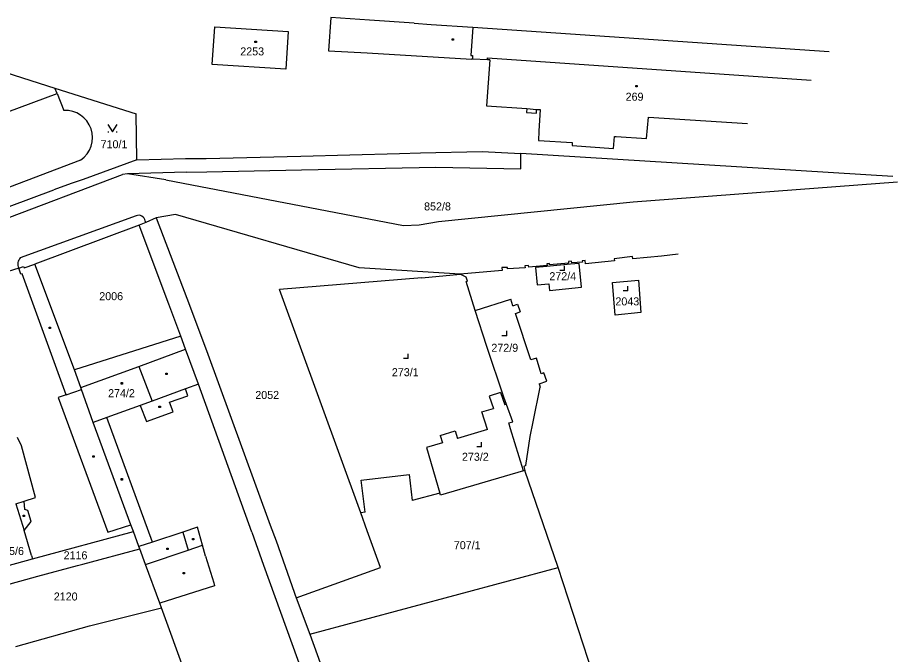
# Model space of a CAD drawing. Extents: x -711879 to -711361, y -1048782 to -1048177.
# Drawn here: x -711557.6 to -711370.9, y -1048599.8 to -1048464.6 of the extents above; entities that cross this region are included whole.
import ezdxf

# ---------------------------------------------------------------- set-up
doc = ezdxf.new("R2010")
doc.units = 0
for name, color, linetype in [('Vrstva 1', 7, 'Continuous'), ('Vrstva 14', 7, 'Continuous'), ('Vrstva 15', 7, 'Continuous'), ('Vrstva 2', 7, 'Continuous'), ('Vrstva 23', 7, 'Continuous'), ('Vrstva 25', 7, 'Continuous'), ('Vrstva 46', 7, 'Continuous')]:
    doc.layers.add(name, color=color, linetype=linetype)

msp = doc.modelspace()

# ---------------------------------------------------------------- linework, layer by layer
at = {"layer": 'Vrstva 1'}
for p, q in [((-711473.47, -1048465.82), (-711482.93, -1048465.18)), ((-711473.47, -1048465.82), (-711469.86, -1048466.07)), ((-711469.86, -1048466.07), (-711460.98, -1048466.67)), ((-711460.98, -1048466.67), (-711385.33, -1048471.82)), ((-711575.44, -1048471.4), (-711549.72, -1048479.57)), ((-711483.41, -1048472.14), (-711461.31, -1048473.42)), ((-711461.08, -1048473.43), (-711461.31, -1048473.42)), ((-711457.91, -1048473.59), (-711461.08, -1048473.43)), ((-711457.37, -1048473.6), (-711458.13, -1048483.34)), ((-711457.37, -1048473.6), (-711457.91, -1048473.59)), ((-711549.25, -1048480.75), (-711549.72, -1048479.57)), ((-711549.72, -1048479.57), (-711532.44, -1048485.06)), ((-711549.25, -1048480.75), (-711547.81, -1048484.31)), ((-711458.13, -1048483.34), (-711449.56, -1048483.95)), ((-711447.47, -1048484.1), (-711446.7, -1048484.15)), ((-711532.35, -1048494.8), (-711532.44, -1048485.06)), ((-711446.7, -1048484.15), (-711446.97, -1048488.76)), ((-711424.12, -1048490.31), (-711423.75, -1048485.73)), ((-711423.75, -1048485.73), (-711402.67, -1048487.12)), ((-711430.94, -1048489.85), (-711430.57, -1048489.87)), ((-711430.57, -1048489.87), (-711424.12, -1048490.31)), ((-711476.59, -1048493.47), (-711472.1, -1048493.36)), ((-711472.1, -1048493.36), (-711459, -1048493.05)), ((-711459, -1048493.05), (-711450.84, -1048493.44)), ((-711371.84, -1048498.35), (-711450.84, -1048493.44)), ((-711544.25, -1048494.85), (-711560.87, -1048501.16)), ((-711532.35, -1048494.8), (-711543.69, -1048498.96)), ((-711532.35, -1048494.8), (-711522.01, -1048494.53)), ((-711522.01, -1048494.53), (-711517.63, -1048494.53)), ((-711517.63, -1048494.53), (-711497.52, -1048494.02)), ((-711497.52, -1048494.02), (-711487.1, -1048493.75)), ((-711487.1, -1048493.75), (-711476.59, -1048493.47)), ((-711543.69, -1048498.96), (-711546.24, -1048499.86)), ((-711546.24, -1048499.86), (-711549.96, -1048501.2)), ((-711559.44, -1048504.71), (-711549.96, -1048501.2)), ((-711524.13, -1048506.41), (-711528.19, -1048507.13)), ((-711485.15, -1048517.73), (-711524.13, -1048506.41)), ((-711530.44, -1048508.12), (-711531.84, -1048508.65)), ((-711528.19, -1048507.13), (-711530.44, -1048508.12)), ((-711528.19, -1048507.13), (-711521.72, -1048524.2)), ((-711531.84, -1048508.65), (-711553.95, -1048516.92)), ((-711525.53, -1048525.42), (-711531.84, -1048508.65)), ((-711427.11, -1048515.34), (-711430.99, -1048515.8)), ((-711430.99, -1048515.8), (-711430.95, -1048516.28)), ((-711427.05, -1048515.84), (-711427.11, -1048515.34)), ((-711420.96, -1048515.29), (-711427.05, -1048515.84)), ((-711417.45, -1048514.81), (-711420.96, -1048515.29)), ((-711557.41, -1048517.79), (-711556.37, -1048517.43)), ((-711556.37, -1048517.43), (-711556.22, -1048517.76)), ((-711556.22, -1048517.76), (-711553.95, -1048516.92)), ((-711545.57, -1048539.39), (-711553.95, -1048516.92)), ((-711463.67, -1048519.09), (-711485.15, -1048517.73)), ((-711453.68, -1048517.63), (-711454.83, -1048517.69)), ((-711454.83, -1048517.69), (-711454.78, -1048518.29)), ((-711453.64, -1048517.98), (-711453.68, -1048517.63)), ((-711449.16, -1048517.22), (-711449.96, -1048517.32)), ((-711449.96, -1048517.32), (-711449.91, -1048517.74)), ((-711449.11, -1048517.59), (-711449.16, -1048517.22)), ((-711445.26, -1048517.25), (-711449.11, -1048517.59)), ((-711445.3, -1048517.43), (-711447.73, -1048517.67)), ((-711447.73, -1048517.67), (-711447.34, -1048521.37)), ((-711440.3, -1048516.97), (-711445.3, -1048517.43)), ((-711444.74, -1048516.84), (-711445.28, -1048516.89)), ((-711445.28, -1048516.89), (-711445.26, -1048517.25)), ((-711444.71, -1048517.11), (-711444.74, -1048516.84)), ((-711440.71, -1048516.72), (-711444.71, -1048517.11)), ((-711440.05, -1048516.33), (-711440.73, -1048516.39)), ((-711440.73, -1048516.39), (-711440.71, -1048516.72)), ((-711438.44, -1048516.83), (-711440.3, -1048516.97)), ((-711440.01, -1048516.66), (-711440.05, -1048516.33)), ((-711437.75, -1048516.54), (-711440.01, -1048516.66)), ((-711437.92, -1048521.86), (-711438.44, -1048516.83)), ((-711437.13, -1048516.17), (-711437.77, -1048516.22)), ((-711437.77, -1048516.22), (-711437.75, -1048516.54)), ((-711437.08, -1048516.85), (-711437.13, -1048516.17)), ((-711430.95, -1048516.28), (-711437.08, -1048516.85)), ((-711557.41, -1048517.79), (-711560.97, -1048518.96)), ((-711471.8, -1048519.84), (-711463.67, -1048519.09)), ((-711454.78, -1048518.29), (-711463.67, -1048519.09)), ((-711462.39, -1048519.72), (-711463.67, -1048519.09)), ((-711449.91, -1048517.74), (-711453.64, -1048517.98)), ((-711471.8, -1048519.84), (-711502.02, -1048522.33)), ((-711462.42, -1048520.66), (-711462.13, -1048520.55)), ((-711460.54, -1048526.78), (-711462.42, -1048520.66)), ((-711462.13, -1048520.55), (-711462.39, -1048519.72)), ((-711447.34, -1048521.37), (-711444.88, -1048521.15)), ((-711444.88, -1048521.15), (-711444.75, -1048522.51)), ((-711431.35, -1048520.88), (-711425.82, -1048520.37)), ((-711430.8, -1048527.75), (-711431.35, -1048520.88)), ((-711425.82, -1048520.37), (-711425.32, -1048527.24)), ((-711484.79, -1048569.75), (-711502.02, -1048522.33)), ((-711444.75, -1048522.51), (-711437.92, -1048521.86)), ((-711521.72, -1048524.2), (-711517.53, -1048535.25)), ((-711460.54, -1048526.78), (-711452.95, -1048524.36)), ((-711452.48, -1048525.77), (-711452.95, -1048524.36)), ((-711523.01, -1048532.21), (-711525.53, -1048525.42)), ((-711458.05, -1048534.42), (-711460.54, -1048526.78)), ((-711452.48, -1048525.77), (-711451.53, -1048525.45)), ((-711451.53, -1048525.45), (-711450.95, -1048527.1)), ((-711451.93, -1048527.44), (-711450.95, -1048527.1)), ((-711448.68, -1048537.29), (-711451.93, -1048527.44)), ((-711425.32, -1048527.24), (-711430.8, -1048527.75)), ((-711523.01, -1048532.21), (-711545.57, -1048539.39)), ((-711521.97, -1048535.01), (-711523.01, -1048532.21)), ((-711454.4, -1048545.16), (-711458.05, -1048534.42)), ((-711519.23, -1048542.39), (-711521.97, -1048535.01)), ((-711517.53, -1048535.25), (-711509.85, -1048556.43)), ((-711447.52, -1048536.9), (-711448.68, -1048537.29)), ((-711446.49, -1048540.23), (-711447.52, -1048536.9)), ((-711544.23, -1048543.15), (-711545.57, -1048539.39)), ((-711445.91, -1048540), (-711446.49, -1048540.23)), ((-711445.29, -1048541.76), (-711445.91, -1048540)), ((-711446.94, -1048542.35), (-711445.29, -1048541.76)), ((-711544.1, -1048543.52), (-711544.23, -1048543.15)), ((-711541.58, -1048550.58), (-711544.1, -1048543.52)), ((-711519.23, -1048542.39), (-711522.03, -1048543.41)), ((-711521.5, -1048544.88), (-711522.03, -1048543.41)), ((-711507.9, -1048573.82), (-711519.23, -1048542.39)), ((-711448.2, -1048550.39), (-711446.71, -1048543.05)), ((-711446.94, -1048542.35), (-711446.87, -1048542.57)), ((-711446.87, -1048542.57), (-711446.71, -1048543.05)), ((-711525.38, -1048546.26), (-711521.5, -1048544.88)), ((-711455.14, -1048544.19), (-711457.51, -1048544.97)), ((-711457.51, -1048544.97), (-711456.65, -1048547.57)), ((-711455.14, -1048544.19), (-711454.21, -1048546.83)), ((-711453.87, -1048546.71), (-711454.4, -1048545.16)), ((-711531.59, -1048546.92), (-711538.69, -1048549.52)), ((-711531.59, -1048546.92), (-711530.27, -1048550.33)), ((-711524.62, -1048548.3), (-711525.38, -1048546.26)), ((-711459.12, -1048548.31), (-711456.65, -1048547.57)), ((-711453.87, -1048546.71), (-711454.21, -1048546.83)), ((-711452.49, -1048550.39), (-711453.87, -1048546.71)), ((-711530.27, -1048550.33), (-711524.62, -1048548.3)), ((-711457.86, -1048552.01), (-711459.12, -1048548.31)), ((-711533.58, -1048572.27), (-711541.58, -1048550.58)), ((-711529.01, -1048575.92), (-711538.69, -1048549.52)), ((-711453.39, -1048550.65), (-711452.49, -1048550.39)), ((-711453, -1048551.92), (-711453.39, -1048550.65)), ((-711448.82, -1048553.5), (-711448.2, -1048550.39)), ((-711467.92, -1048553.33), (-711464.78, -1048552.31)), ((-711464.78, -1048552.31), (-711464.24, -1048553.92)), ((-711457.86, -1048552.01), (-711464.24, -1048553.92)), ((-711450.27, -1048560.84), (-711453, -1048551.92)), ((-711556.81, -1048555.48), (-711557.67, -1048553.71)), ((-711467.43, -1048554.88), (-711470.82, -1048555.89)), ((-711467.92, -1048553.33), (-711467.43, -1048554.88)), ((-711449.72, -1048559.71), (-711448.82, -1048553.5)), ((-711553.85, -1048566.46), (-711556.81, -1048555.48)), ((-711509.85, -1048556.43), (-711504.02, -1048572.33)), ((-711470.82, -1048555.89), (-711468.01, -1048565.56)), ((-711449.72, -1048559.71), (-711450.2, -1048559.86)), ((-711450.2, -1048559.86), (-711449.94, -1048560.74)), ((-711484.7, -1048562.79), (-711474.54, -1048561.6)), ((-711474.54, -1048561.6), (-711473.86, -1048567.13)), ((-711450.27, -1048560.84), (-711467.89, -1048565.98)), ((-711449.94, -1048560.74), (-711450.27, -1048560.84)), ((-711442.86, -1048581.35), (-711449.94, -1048560.74)), ((-711483.89, -1048569.55), (-711484.7, -1048562.79)), ((-711468.01, -1048565.56), (-711473.86, -1048567.13)), ((-711467.89, -1048565.98), (-711468.01, -1048565.56)), ((-711558, -1048567.81), (-711556.26, -1048567.22)), ((-711556.26, -1048567.22), (-711553.85, -1048566.46)), ((-711483.89, -1048569.55), (-711484.79, -1048569.75)), ((-711483.41, -1048573.55), (-711484.79, -1048569.75)), ((-711554.45, -1048579.51), (-711533.06, -1048573.69)), ((-711533.06, -1048573.69), (-711533.58, -1048572.27)), ((-711531.88, -1048576.89), (-711533.06, -1048573.69)), ((-711519.46, -1048572.8), (-711522.53, -1048573.8)), ((-711518.39, -1048576.61), (-711519.46, -1048572.8)), ((-711504.02, -1048572.33), (-711502.76, -1048575.7)), ((-711480.59, -1048581.32), (-711483.41, -1048573.55)), ((-711522.53, -1048573.8), (-711529.01, -1048575.92)), ((-711507.9, -1048573.82), (-711505.42, -1048580.81)), ((-711543.79, -1048580.61), (-711531.71, -1048577.35)), ((-711531.71, -1048577.35), (-711531.88, -1048576.89)), ((-711530.48, -1048580.69), (-711531.71, -1048577.35)), ((-711517.73, -1048578.95), (-711518.39, -1048576.61)), ((-711502.76, -1048575.7), (-711498.95, -1048586.55)), ((-711517.73, -1048578.95), (-711516.01, -1048584.55)), ((-711562.83, -1048581.76), (-711554.45, -1048579.51)), ((-711553.36, -1048583.2), (-711544.91, -1048580.91)), ((-711544.91, -1048580.91), (-711543.79, -1048580.61)), ((-711527.46, -1048588.87), (-711530.48, -1048580.69)), ((-711505.42, -1048580.81), (-711488.95, -1048626.45)), ((-711498.5, -1048587.73), (-711482.4, -1048581.96)), ((-711495.62, -1048595.46), (-711442.86, -1048581.35)), ((-711482.4, -1048581.96), (-711480.59, -1048581.32)), ((-711434.36, -1048607.51), (-711442.86, -1048581.35)), ((-711561.81, -1048585.49), (-711553.36, -1048583.2)), ((-711516.01, -1048584.55), (-711515.82, -1048585.22)), ((-711515.82, -1048585.22), (-711527.46, -1048588.87)), ((-711498.95, -1048586.55), (-711498.79, -1048586.96)), ((-711498.79, -1048586.96), (-711498.5, -1048587.73)), ((-711498.5, -1048587.73), (-711495.62, -1048595.46)), ((-711542.36, -1048593.72), (-711527.11, -1048589.92)), ((-711527.11, -1048589.92), (-711527.46, -1048588.87)), ((-711520.21, -1048608.66), (-711527.11, -1048589.92)), ((-711557.98, -1048598.11), (-711542.36, -1048593.72)), ((-711495.62, -1048595.46), (-711482.57, -1048631.65))]:
    msp.add_line(p, q, dxfattribs=at)
for points in [[(-711482.93, -1048465.18), (-711491.12, -1048464.63), (-711491.67, -1048471.66), (-711483.41, -1048472.14)], [(-711515.8, -1048466.56), (-711500.18, -1048467.58), (-711500.7, -1048475.56), (-711516.32, -1048474.55), (-711515.8, -1048466.56)], [(-711449.56, -1048483.95), (-711449.61, -1048484.76), (-711447.52, -1048484.9), (-711447.47, -1048484.1)], [(-711446.97, -1048488.76), (-711447.1, -1048490.68), (-711439.89, -1048491.17), (-711439.93, -1048491.77), (-711431.11, -1048492.38), (-711430.94, -1048489.85)]]:
    msp.add_lwpolyline(points, dxfattribs=at)
msp.add_arc((-711547.524, -1048490.085), 5.782, 304.49178, 92.83413, dxfattribs=at)
at = {"layer": 'Vrstva 2'}
for p, q in [((-711460.98, -1048466.67), (-711461.45, -1048472.65)), ((-711461.45, -1048472.65), (-711461.04, -1048472.65)), ((-711461.04, -1048472.65), (-711461.08, -1048473.43)), ((-711457.91, -1048473.59), (-711457.89, -1048473.19)), ((-711457.89, -1048473.19), (-711389.22, -1048477.89)), ((-711559.72, -1048484.64), (-711549.25, -1048480.75)), ((-711449.56, -1048483.95), (-711447.47, -1048484.1)), ((-711450.78, -1048496.73), (-711450.84, -1048493.44)), ((-711517.49, -1048497.39), (-711497.39, -1048496.93)), ((-711497.39, -1048496.93), (-711468.85, -1048496.38)), ((-711468.85, -1048496.38), (-711450.78, -1048496.73)), ((-711562.32, -1048508.09), (-711535.4, -1048497.92)), ((-711534.31, -1048497.75), (-711535.4, -1048497.92)), ((-711521.87, -1048497.44), (-711534.31, -1048497.75)), ((-711526.19, -1048499.09), (-711534.31, -1048497.75)), ((-711521.87, -1048497.44), (-711517.49, -1048497.39)), ((-711526.19, -1048499.09), (-711475.74, -1048508.78)), ((-711426.99, -1048503.71), (-711370.88, -1048499.49)), ((-711468.31, -1048507.91), (-711426.99, -1048503.71)), ((-711532.48, -1048506.69), (-711557.07, -1048515.58)), ((-711530.44, -1048508.12), (-711530.54, -1048507.78)), ((-711472.38, -1048508.62), (-711468.31, -1048507.91)), ((-711475.74, -1048508.78), (-711472.38, -1048508.62)), ((-711556.96, -1048519.09), (-711557.41, -1048517.79)), ((-711556.7, -1048518.99), (-711556.96, -1048519.09)), ((-711547.3, -1048544.68), (-711556.7, -1048518.99)), ((-711531.9, -1048538.64), (-711521.97, -1048535.01)), ((-711544.23, -1048543.15), (-711531.9, -1048538.64)), ((-711531.9, -1048538.64), (-711529.08, -1048546)), ((-711547.3, -1048544.68), (-711544.1, -1048543.52)), ((-711522.03, -1048543.41), (-711529.08, -1048546)), ((-711547.3, -1048544.68), (-711549.03, -1048545.28)), ((-711549.03, -1048545.28), (-711538.47, -1048573.84)), ((-711529.08, -1048546), (-711531.59, -1048546.92)), ((-711538.69, -1048549.52), (-711541.58, -1048550.58)), ((-711558, -1048567.81), (-711556.25, -1048573.47)), ((-711556.08, -1048568.99), (-711556.26, -1048567.22)), ((-711555.5, -1048569.22), (-711556.08, -1048568.99)), ((-711554.78, -1048571.56), (-711555.5, -1048569.22)), ((-711556.25, -1048573.47), (-711554.78, -1048571.56)), ((-711554.67, -1048578.78), (-711556.25, -1048573.47)), ((-711538.47, -1048573.84), (-711533.58, -1048572.27)), ((-711522.53, -1048573.8), (-711521.43, -1048577.64)), ((-711529.01, -1048575.92), (-711531.88, -1048576.89)), ((-711521.43, -1048577.64), (-711518.39, -1048576.61)), ((-711554.67, -1048578.78), (-711554.45, -1048579.51)), ((-711530.48, -1048580.69), (-711521.43, -1048577.64))]:
    msp.add_line(p, q, dxfattribs=at)
for centre, radius, start, end in [((-711531.944, -1048508.007), 1.422, 9.20144, 112.13915), ((-711555.629, -1048516.933), 1.977, 136.81148, 205.69619)]:
    msp.add_arc(centre, radius, start, end, dxfattribs=at)
at = {"layer": 'Vrstva 23'}
for p, q in [((-711538.48, -1048487.35), (-711537.48, -1048488.85)), ((-711537.48, -1048488.85), (-711536.48, -1048487.35)), ((-711538.48, -1048488.85), (-711538.28, -1048488.85)), ((-711536.68, -1048488.85), (-711536.48, -1048488.85)), ((-711441.52, -1048518.33), (-711441.52, -1048517.33)), ((-711441.52, -1048518.33), (-711442.52, -1048518.33)), ((-711428.07, -1048522.64), (-711429.07, -1048522.64)), ((-711428.07, -1048522.64), (-711428.07, -1048521.64)), ((-711453.82, -1048532.13), (-711454.82, -1048532.13)), ((-711453.82, -1048532.13), (-711453.82, -1048531.13)), ((-711474.72, -1048536.99), (-711474.72, -1048535.99)), ((-711474.72, -1048536.99), (-711475.72, -1048536.99)), ((-711459.15, -1048555.75), (-711459.15, -1048554.75)), ((-711459.15, -1048555.75), (-711460.15, -1048555.75))]:
    msp.add_line(p, q, dxfattribs=at)
at = {"layer": 'Vrstva 25'}
for p, q in [((-711465.4, -1048469.14), (-711465.1, -1048469.14)), ((-711465.4, -1048469.44), (-711465.4, -1048469.14)), ((-711465.1, -1048469.14), (-711465.1, -1048469.44)), ((-711507.25, -1048469.64), (-711506.95, -1048469.64)), ((-711507.25, -1048469.94), (-711507.25, -1048469.64)), ((-711506.95, -1048469.94), (-711507.25, -1048469.94)), ((-711506.95, -1048469.64), (-711506.95, -1048469.94)), ((-711465.1, -1048469.44), (-711465.4, -1048469.44)), ((-711426.41, -1048479.01), (-711426.11, -1048479.01)), ((-711426.41, -1048479.31), (-711426.41, -1048479.01)), ((-711426.11, -1048479.31), (-711426.41, -1048479.31)), ((-711426.11, -1048479.01), (-711426.11, -1048479.31)), ((-711550.94, -1048530.33), (-711550.64, -1048530.33)), ((-711550.94, -1048530.63), (-711550.94, -1048530.33)), ((-711550.64, -1048530.63), (-711550.94, -1048530.63)), ((-711550.64, -1048530.33), (-711550.64, -1048530.63)), ((-711526.18, -1048540.06), (-711525.88, -1048540.06)), ((-711526.18, -1048540.36), (-711526.18, -1048540.06)), ((-711525.88, -1048540.06), (-711525.88, -1048540.36)), ((-711525.88, -1048540.36), (-711526.18, -1048540.36)), ((-711535.64, -1048542.1), (-711535.34, -1048542.1)), ((-711535.64, -1048542.4), (-711535.64, -1048542.1)), ((-711535.34, -1048542.4), (-711535.64, -1048542.4)), ((-711535.34, -1048542.1), (-711535.34, -1048542.4)), ((-711527.63, -1048547.09), (-711527.33, -1048547.09)), ((-711527.63, -1048547.39), (-711527.63, -1048547.09)), ((-711527.33, -1048547.39), (-711527.63, -1048547.39)), ((-711527.33, -1048547.09), (-711527.33, -1048547.39)), ((-711541.68, -1048557.6), (-711541.38, -1048557.6)), ((-711541.68, -1048557.9), (-711541.68, -1048557.6)), ((-711541.38, -1048557.9), (-711541.68, -1048557.9)), ((-711541.38, -1048557.6), (-711541.38, -1048557.9)), ((-711535.64, -1048562.46), (-711535.34, -1048562.46)), ((-711535.64, -1048562.76), (-711535.64, -1048562.46)), ((-711535.34, -1048562.46), (-711535.34, -1048562.76)), ((-711535.34, -1048562.76), (-711535.64, -1048562.76)), ((-711556.47, -1048570.21), (-711556.17, -1048570.21)), ((-711556.47, -1048570.51), (-711556.47, -1048570.21)), ((-711556.17, -1048570.51), (-711556.47, -1048570.51)), ((-711556.17, -1048570.21), (-711556.17, -1048570.51)), ((-711520.54, -1048575.14), (-711520.24, -1048575.14)), ((-711520.54, -1048575.44), (-711520.54, -1048575.14)), ((-711520.24, -1048575.44), (-711520.54, -1048575.44)), ((-711520.24, -1048575.14), (-711520.24, -1048575.44)), ((-711525.99, -1048577.24), (-711525.69, -1048577.24)), ((-711525.99, -1048577.54), (-711525.99, -1048577.24)), ((-711525.69, -1048577.24), (-711525.69, -1048577.54)), ((-711525.69, -1048577.54), (-711525.99, -1048577.54)), ((-711522.51, -1048582.37), (-711522.21, -1048582.37)), ((-711522.51, -1048582.67), (-711522.51, -1048582.37)), ((-711522.21, -1048582.67), (-711522.51, -1048582.67)), ((-711522.21, -1048582.37), (-711522.21, -1048582.67))]:
    msp.add_line(p, q, dxfattribs=at)
at = {"layer": 'Vrstva 46'}
for p, q in [((-711457.89, -1048473.19), (-711457.89, -1048473.19)), ((-711457.37, -1048473.6), (-711457.37, -1048473.6)), ((-711458.13, -1048483.34), (-711458.13, -1048483.34)), ((-711446.7, -1048484.15), (-711446.7, -1048484.15)), ((-711423.75, -1048485.73), (-711423.75, -1048485.73)), ((-711446.97, -1048488.76), (-711446.97, -1048488.76)), ((-711430.94, -1048489.85), (-711430.94, -1048489.85)), ((-711430.57, -1048489.87), (-711430.57, -1048489.87)), ((-711424.12, -1048490.31), (-711424.12, -1048490.31)), ((-711468.31, -1048507.91), (-711468.31, -1048507.91)), ((-711430.99, -1048515.8), (-711430.99, -1048515.8)), ((-711440.3, -1048516.97), (-711440.3, -1048516.97)), ((-711437.08, -1048516.85), (-711437.08, -1048516.85)), ((-711430.95, -1048516.28), (-711430.95, -1048516.28)), ((-711431.35, -1048520.88), (-711431.35, -1048520.88)), ((-711425.82, -1048520.37), (-711425.82, -1048520.37)), ((-711502.02, -1048522.33), (-711502.02, -1048522.33)), ((-711452.95, -1048524.36), (-711452.95, -1048524.36)), ((-711430.8, -1048527.75), (-711430.8, -1048527.75)), ((-711425.32, -1048527.24), (-711425.32, -1048527.24)), ((-711547.3, -1048544.68), (-711547.3, -1048544.68)), ((-711459.12, -1048548.31), (-711459.12, -1048548.31)), ((-711541.58, -1048550.58), (-711541.58, -1048550.58)), ((-711457.86, -1048552.01), (-711457.86, -1048552.01)), ((-711556.26, -1048567.22), (-711556.26, -1048567.22)), ((-711473.86, -1048567.13), (-711473.86, -1048567.13)), ((-711556.08, -1048568.99), (-711556.08, -1048568.99)), ((-711555.5, -1048569.22), (-711555.5, -1048569.22)), ((-711484.79, -1048569.75), (-711484.79, -1048569.75)), ((-711483.89, -1048569.55), (-711483.89, -1048569.55)), ((-711554.78, -1048571.56), (-711554.78, -1048571.56)), ((-711556.25, -1048573.47), (-711556.25, -1048573.47)), ((-711533.06, -1048573.69), (-711533.06, -1048573.69)), ((-711483.41, -1048573.55), (-711483.41, -1048573.55)), ((-711538.47, -1048573.84), (-711538.47, -1048573.84)), ((-711554.67, -1048578.78), (-711554.67, -1048578.78)), ((-711554.45, -1048579.51), (-711554.45, -1048579.51)), ((-711544.91, -1048580.91), (-711544.91, -1048580.91)), ((-711498.79, -1048586.96), (-711498.79, -1048586.96)), ((-711498.5, -1048587.73), (-711498.5, -1048587.73)), ((-711542.36, -1048593.72), (-711542.36, -1048593.72))]:
    msp.add_line(p, q, dxfattribs=at)

# ---------------------------------------------------------------- texts
at = {"layer": 'Vrstva 14'}
for s, p in [('710/1', (-711540.02, -1048492.36)), ('852/8', (-711471.35, -1048505.55)), ('2006', (-711540.3, -1048524.6)), ('2052', (-711507.18, -1048545.56)), ('707/1', (-711465.04, -1048577.44)), ('2116', (-711547.873, -1048579.59)), ('2120', (-711549.959, -1048588.33))]:
    msp.add_text(s, height=1.7, dxfattribs=at).set_placement(p)
at = {"layer": 'Vrstva 15'}
for s, p in [('2253', (-711510.37, -1048472.65)), ('269', (-711428.57, -1048482.27)), ('272/4', (-711444.76, -1048520.36)), ('2043', (-711430.74, -1048525.7)), ('272/9', (-711457.07, -1048535.55)), ('273/1', (-711478.19, -1048540.73)), ('274/2', (-711538.43, -1048545.18)), ('273/2', (-711463.31, -1048558.68)), ('275/6', (-711561.98, -1048578.67))]:
    msp.add_text(s, height=1.7, dxfattribs=at).set_placement(p)

doc.saveas('drawing.dxf')
